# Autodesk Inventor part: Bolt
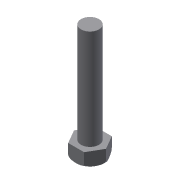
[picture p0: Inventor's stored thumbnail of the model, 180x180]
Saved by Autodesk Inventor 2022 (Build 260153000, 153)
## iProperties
Created: 2002-02
Part Number: Bolt
Document SubType Name: Modeling
Designer: ***
Density: 1 g/cm^3
Material: Generic
Appearance: Default
Control State: 0
Master: False
Checked Out: False
Shininess: 77.0
Length Units: 11269
Angle Units: 11279
Time Units: 11290
Mass Units: 11283
Length Display Precision: 3
Angle Display Precision: 2
Density: 0.0
Volumn: 0.0
Area: 0.0
PropertySet Name: Model Information
Author: ***
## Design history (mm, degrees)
sketch "Sketch1"
  geometry: C1 r 4 at (0, 0)
  constraints: 1 centre point
  dimensions: "d0" = 8 diameter of C1
extrude "Extrusion1" new body sketch "Sketch1" stored distance "d1" = 3.5; taper "d2" = 0 deg
fillet "Fillet1" dims "d3" = 1
sketch "Sketch2"
  geometry: L1 (4, 0)-(2, -3.464); L2 (2, -3.464)-(-2, -3.464); L3 (-2, -3.464)-(-4, 0); L4 (-4, 0)-(-2, 3.464); L5 (-2, 3.464)-(2, 3.464); L6 (2, 3.464)-(4, 0); 2 further points
  constraints: 12 end point, 1 coincident, 11 other
extrude "Extrusion2" sketch "Sketch2" extent not by distance; stored distance "d4" = 3.5; taper "d5" = 0 deg
sketch "Sketch3"
  geometry: C1 r 2.25 at (0, 0)
  constraints: 1 centre point
  dimensions: "d6" = 4.5 diameter of C1
extrude "Extrusion3" join sketch "Sketch3" distance "d7" = 25; taper "d8" = 0 deg
body "Solid1"
